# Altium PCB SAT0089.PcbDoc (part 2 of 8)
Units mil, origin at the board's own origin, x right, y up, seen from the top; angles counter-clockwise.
Board outline 4075 x 2715 mil, 6 copper layers (Top Layer, InternalPlane1, MidLayer1, Internal Plane 3, InternalPlane2, Bottom Layer), stack 67.4 mil thick; 538 components, 405 nets, 1716 pads, 1236 vias.
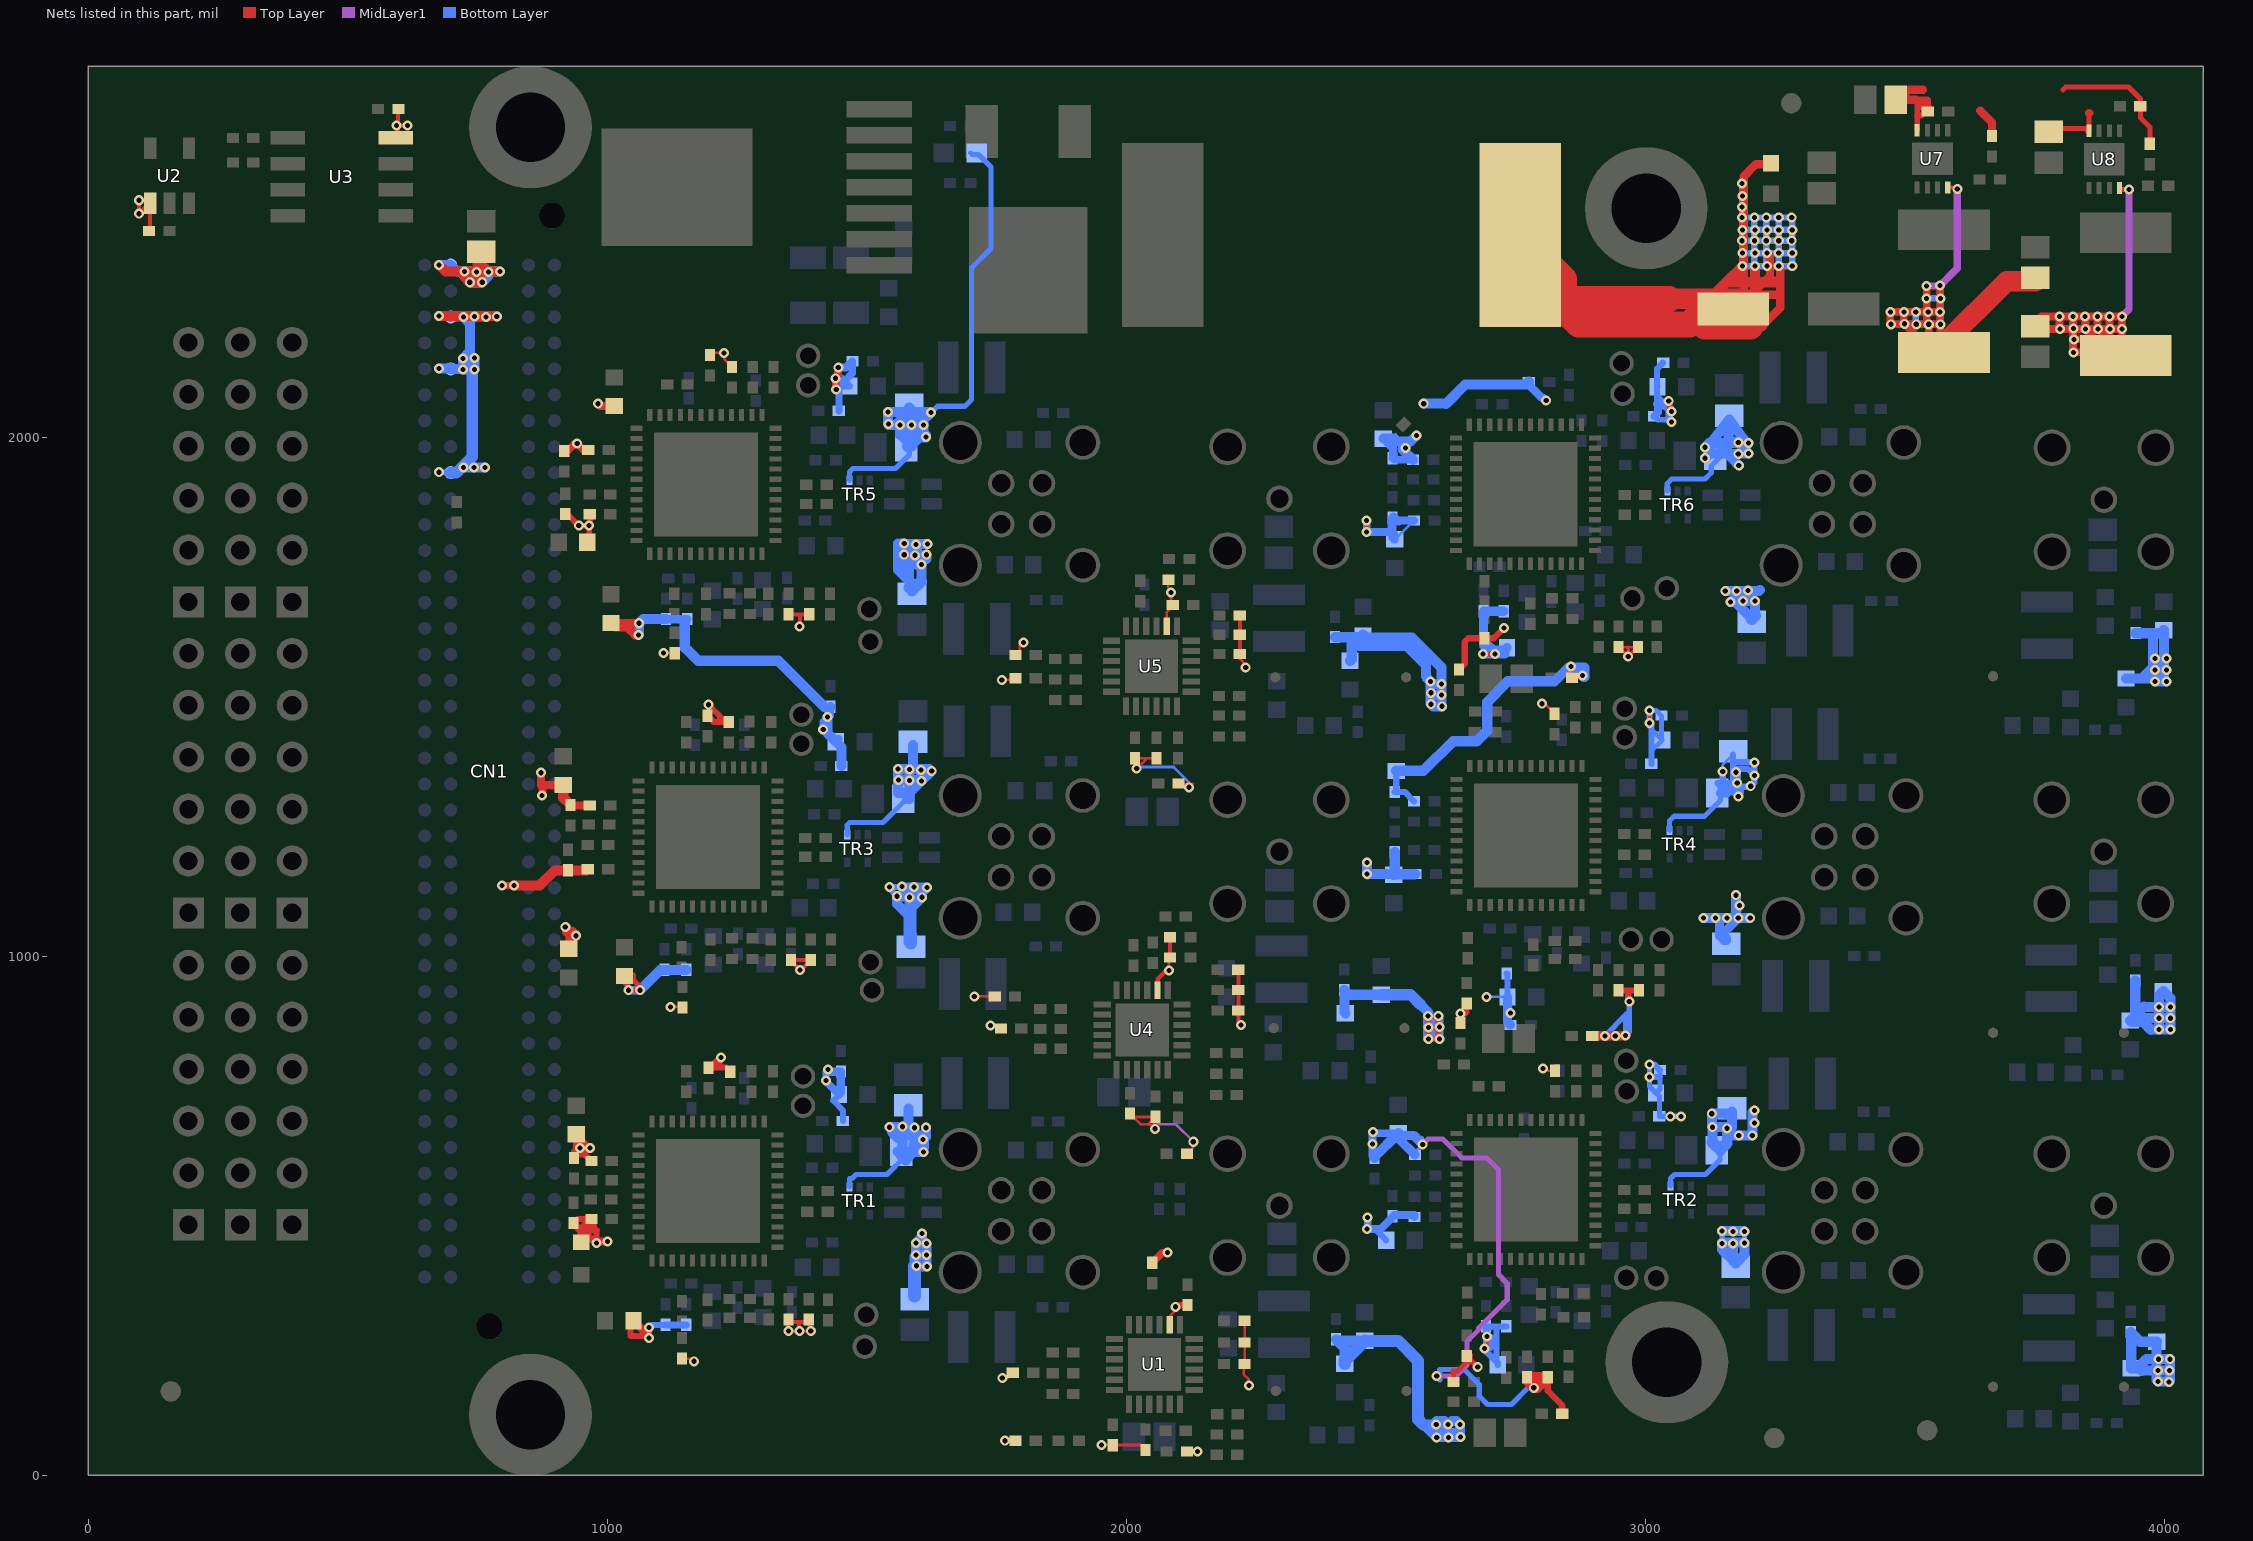
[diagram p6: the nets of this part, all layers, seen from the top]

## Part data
C1 C12 C13 C14 C15: "CAP, CERM, 10uF, 10V, +/-10%, X7R, 0805"
C2 C3 C4 C5 C6 C16 C18 C23 C24 C25 C27 C28 C30 C31 C32 C33 C35 C36 C37 C41 C44 C45 C48 C50 C55 C56 C57 C59 C60 C62 C63 C64 C65 C67 C68 C69 C73 C77 C79 C80 C82 C87 C88 C89 C91 C92 C94 C95 C96 C97 C99 C100 C101 C105 C109 C111 C112 C115 C119 C120 C121 C123 C126 C127 C129 C130 C131 C132 C133 C134 C136 C141 C142 C144 C146 C151 C152 C153 C155 C156 C158 C159 C160 C161 C163 C164 C165 C169 C173 C175 C176 C178 C183 C184 C185 C186 C187 C189 C190 C191 C192 C194 C195 C196 C200 C204 C206 C208 C209 C210 C211 C212 C213: "CAP, CERM, 0.1uF, 16V, +/-10%, X7R, 0402"
C7 C8: "CAP, CERM, 10uF, 25V, +/-10%, X7R, 1206"
C9: "CAP, CERM, 0.1uF, 50V, +/-10%, X7R, 0603"
C10: "CAP, CERM, 0.01uF, 50V, +/-10%, X7R, 0603"
C11: "CAP, AL, 82uF, 10V, +/-20%, 0.023 ohm, SMD"
C17 C19 C29 C34 C38 C39 C40 C42 C43 C46 C49 C51 C61 C66 C70 C71 C72 C74 C76 C78 C81 C83 C93 C98 C102 C103 C104 C106 C108 C110 C113 C114 C124 C125 C128 C135 C137 C138 C140 C143 C145 C147 C157 C162 C166 C167 C168 C170 C172 C174 C177 C179 C188 C193 C197 C198 C199 C201 C203 C205: "CAP CER 4.7UF 25V 10% X5R 0603"
C20 C21 C52 C53 C84 C85 C116 C117 C148 C149 C180 C181: "CAP CER 0.1UF 100V 10% X7R 0603"
C22 C54 C86 C118 C150 C182: "CAP, CERM, 10uF, 16V, +/-10%, X5R, 0805"
C26 C58 C90 C122 C154 C207: "CAP, CERM, 0.047uF, 16V, +/-10%, X7R, 0402"
C47 C75 C107 C139 C171 C202: "CAP, CERM, 22uF, 6.3V, +/-10%, X5R, 0805"
CN1: "Samtec 50 MIL Pitch Thermal Array Assembly"
CN2 CN3 CN4: library part "3X6 Header 100 MIL PITCH", "3X6 Header 100 MIL PITCH"
CN5 CN7 CN9 CN11 CN13 CN15: "Straight Plug PCB"
CN6 CN8 CN10 CN12 CN14 CN16: "Straight Plug"
D1: "Diode, Schottky, 40V, 7A, DPAK"
FID1 FID2 FID3 FID4 FID5 FID6: "Fiducial mark.  There is nothing to buy or mount."
L1: "Inductor, Drum Core, Ferrite, 4.7uH, 8.5A, 0.0088 ohm, SMD"
L2 L3: "INDUCTOR 2.2UH 1300MA 2220 10%"
L4 L5 L14 L15 L24 L25 L34 L35 L44 L45 L54 L55: "Fixed Inductors Power Inductor 10 uH 10 % 0.59 A"
L6 L16 L26 L36 L46 L56: "CHOKE COMMON MODE 67 OHM 0805"
L7 L17 L27 L37 L47 L57: "FERRITE CHIP 1000 OHM 400MA 0603"
L8 L18 L28 L39 L48 L58: "Fixed Inductors Power Inductor 4.7 uH 10 % 0.95 A"
L9 L19 L29 L38 L49 L59: "Fixed Inductors Power Inductor 100 uH 20 % 1.15 A"
L10 L11 L12 L13 L20 L21 L22 L23 L30 L31 L32 L33 L40 L41 L42 L43 L50 L51 L52 L53 L60 L61 L62 L63: "FERRITE CHIP 1000 OHM 0402"
LD1: "LED, Red, SMD"
Logo1: library part TI_Logo, "Texas Instrument Corporate Signature"
R1 R38 R39 R45 R63 R71 R87 R95 R111 R119 R136 R143 R167: "RES, 0 ohm, 5%, 0.063W, 0402"
R2 R13: "RES, 1.00k ohm, 1%, 0.063W, 0402"
R3: "RES, 15.0k ohm, 1%, 0.063W, 0402"
R4 R5 R6 R9 R12 R17 R18 R19 R20 R21 R22: "RES, 10.0k ohm, 1%, 0.063W, 0402"
R7: "RES, 13.0k ohm, 1%, 0.063W, 0402"
R8 R48 R64 R72 R96 R120 R135 R144 R159 R168: "RES, 3.01k ohm, 1%, 0.063W, 0402"
R10: "RES, 4.99k ohm, 1%, 0.063W, 0402"
R11 R49 R73 R88 R97 R121 R145 R160 R169: "RES, 11.0k ohm, 1%, 0.063W, 0402"
R14: "RES, 5.90k ohm, 1%, 0.1W, 0603"
R15: "RES, 61.9k ohm, 1%, 0.063W, 0402"
R16: "RES, 270 ohm, 5%, 0.125W, 0805"
R23 R24 R25 R50 R51 R52 R74 R75 R76 R98 R99 R101 R122 R123 R124 R146 R147 R148: "RES, 0 ohm, 5%, 0.125W, 0805"
R26 R27 R53 R54 R77 R78 R100 R102 R125 R126 R149 R150: "RES 1.0K OHM 1/10W 5% 0603 SMD"
R28 R29 R30 R55 R56 R57 R79 R80 R81 R103 R104 R105 R127 R128 R129 R151 R152 R153: "RES, 49.9 ohm, 1%, 0.063W, 0402"
R31 R34 R35 R44 R47 R59 R60 R68 R69 R83 R84 R92 R93 R107 R108 R116 R117 R131 R132 R140 R141 R155 R156 R164 R165 R172 R175 R178 R181 R184: "RES 10K OHM 1/16W .1% 0402 SMD"
R32 R36 R37 R58 R61 R62 R82 R85 R86 R106 R109 R110 R130 R133 R134 R154 R157 R158 R185 R186 R187 R188 R189 R190: "RES, 33 ohm, 5%, 0.063W, 0402"
R33 R40 R170 R171 R173 R174 R176 R177 R179 R180 R182 R183: "RES, 130 ohm, 5%, 0.063W, 0402"
R41 R42 R43 R46 R65 R66 R67 R70 R89 R90 R91 R94 R113 R114 R115 R118 R137 R138 R139 R142 R161 R162 R163 R166: "RES, 2.2k ohm, 5%, 0.063W, 0402"
R112: "RES, 100k ohm, 1%, 0.063W, 0402"
TP1 TP2 TP3 TP4 TP5 TP6 TP7 TP8 TP9 TP10 TP11 TP12 TP13 TP14 TP15 TP16 TP17 TP18 TP19 TP20 TP21 TP22 TP23 TP24: library part TP-032_RND, "Test Point, O.032 Hole"
TR1 TR2 TR3 TR4 TR5 TR6: "Low-Capacitance + / - 15 kV ESD-Protection Array for High-Speed Data Interfaces, 2 Channels, -40 to +85 degC, 5-pin SOT (DRL), Green (RoHS & no Sb/Br)"
U1 U4 U5: "IC I/O EXPANDER I2C 16B 24QFN"
U2: "IC ACCEL SMBUS DUAL TSOT23-5"
U3: "IC EEPROM 2KBIT 1MHZ 8SOIC"
U6: "5A SIMPLE SWITCHER®, Step-Down Voltage Regulator with Synchronization or Adjustable Switching Frequency, 7-pin TO-263 Thin, Pb-Free"
U7 U8: "2MHz, 600mA Step-Down DC-DC Converter with Mode Control, 8-pin LLP, Pb-Free"
U9 U10 U11 U12 U13 U14: "FPD-Link III Serializer and Deserializer, RHS0048A"
ZZ2 ZZ3 ZZ4: library part AssemblyNote

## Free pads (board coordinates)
  round 236.22 hole 133.86: 0(852.01,117.01) 0(852.01,2597.32) 0(3001.6,2441.8) 0(3041.61,218.43)
  round 39.37 smd paste-1000 mask-1000: 0(3248.31,72.01)

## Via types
v1: diameter 19.29, hole 9.84, Top Layer to Bottom Layer, tented both sides, 1155 vias
v2: diameter 19.68, hole 7.87, Top Layer to Bottom Layer, tented both sides, 80 vias
v3: diameter 22, hole 10, Top Layer to Bottom Layer, tented both sides, 1 vias

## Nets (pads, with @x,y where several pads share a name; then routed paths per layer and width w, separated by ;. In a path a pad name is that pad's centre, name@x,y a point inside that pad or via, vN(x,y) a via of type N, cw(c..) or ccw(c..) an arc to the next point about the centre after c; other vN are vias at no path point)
+1V8: C12.1 C28.1 C29.1 C60.1 C61.1 C92.1 C93.1 C132.1 C140.1 C156.1 C157.1 C187.1 C188.1 L2.2 L10.2 L20.2 L30.2 L40.2 L50.2 L60.2 R34.1 R35.1 R44.1 R59.1 R60.1 R68.1 R83.1 R84.1 R92.1 R107.1 R108.1 R116.1 R131.1 R132.1 R140.1 R155.1 R156.1 R164.1 U7.4 | length 5438.5
  Top Layer w5: v1@940,635 941,635 945,631 v1(947,631) ; R35.1@1349,300 1347,298 1347,280 v1(1349,278) v1(1370,278) v1(1392,278) 1391,279 1388,279 R34.1@1388,300 ; v1(1738,867) 1738,866 1753,866 R92.1@1758,861 ; v1(1760,1533) 1777,1533 1780,1536 R140.1@1786,1536 ; v1(1761,188) 1771,188 R44.1@1781,198 ; v1(2857,1559) 2857,1539 2860,1536 2874,1536 v1(2879,1541) ; R156.1@2948,1596 2949,1596 2967,1596 2985,1596 R155.1@2986,1596
  Top Layer w7: R156.1@2949,1596 v1(2967,1578) ; 2967,1596 v1(2967,1578) ; R155.1@2985,1596 v1(2967,1578)
  Top Layer w7.87: R35.1@1349,300 1353,296 1369,296 ; v1(1370,278) 1369,279 1369,296 ; R34.1@1388,300 1384,296 1369,296 ; R84.1@1354,991 v1(1371,974) 1373,974 1392,993 1354,993 R84.1@1354,991
  Top Layer w8: R132.1@1349,1659 1371,1659 ; v1(1370,1636) 1371,1637 1371,1659 ; R131.1@1389,1659 1371,1659 ; U7.4@3582.98,2481.43 3598.57,2481.43 v1(3601,2479)
  Top Layer w11.81: R108.1@2948.28,934.37 2967,934.37 ; v1(2969,913) 2967,915 2967,934.37 ; R107.1@2987.65,934.37 2967,934.37
  Top Layer w12: C28.1@936,612 C28.1@936,619 ; C29.1@940,648 940,635 940,624 936,624 C28.1@936,619 ; L10.2@969,606 956,619 C28.1@936,619 ; R59.1@2812,189 2812,163 2840,135 R68.1@2840,119
  Top Layer w15: v1(872,1354) 872,1330 875,1330 ; v1(874,1310) 875,1311 875,1330 ; C93.1@915,1330.5 875.5,1330.5 875,1330 ; C156.1@917,1974 923,1974 937,1988 v1(942,1988) 954,1976 L50.2@963,1976 ; C92.1@929,1292 930,1291 L30.2@966,1291 ; v1(982,2065) 986.5,2060.5 C157.1@1013,2060.5 ; v1(3542,2292) v1(3542,2268) v1@3542,2242 ; v1(3568,2293) v1@3568,2268 ; v1(3569,2218) v1@3568,2218 ; v1(3569,2268) v1@3568,2268 ; v1(3498,2242) 3498,2220 v1(3499,2219) ; v1(3498,2242) v1(3521,2242) v1@3542,2242 ; v1(3498,2242) v1(3472,2242) 3472,2219 v1(3473,2218) v1@3499,2218 ; v1@3499,2218 v1(3499,2219) ; v1@3499,2218 v1@3500,2218 ; v1(3499,2219) v1@3500,2218 ; v1@3500,2218 v1(3522,2218) v1(3546,2218) ; v1@3500,2218 3555.47,2162.53 3575.11,2162.53 L2.2@3568,2169.64 ; v1@3542,2242 v1(3545,2242) v1(3568,2242) ; v1@3542,2242 3542,2222 v1(3546,2218) ; v1(3546,2218) 3546,2191.64 L2.2@3568,2169.64 ; v1(3546,2218) v1@3568,2218 ; L2.2@3568,2169.64 v1@3568,2218 ; v1@3568,2218 v1(3568,2242) ; v1(3568,2242) v1@3568,2268
  Top Layer w18: R116.1@2898,847 v1(2922,847) v1(2942,847) 2961,847 v1(2962,848)
  Top Layer w19.29: C29.1@940,648 C29.1@940,652 ; C29.1@940,657.5 C29.1@940,657.44 C29.1@940,652 ; v1(947,631) v1@961,631 ; v1(967,631) v1@961,631 ; R60.1@2772,189 2772,182 v1(2785,169) ; C29.1@940,652 v1@961,631
  Top Layer w19.68: C93.1@915,1330.5 C93.1@915,1330.44 915,1306 C92.1@929,1292
  Top Layer w20: R60.1@2772,189 2812,189 2792,169 v1(2785,169)
  Top Layer w39: L2.2@3575.11,2162.53 3575.11,2180.11 3696,2301 C12.1@3751,2301
  MidLayer1 w9.84: v1(2571,638) 2581,648 2610,648 2646,612 2694,612 2717,589 2717,387 2734,370 2734,339 2679,284 2679,281 2656,258 2656,212 2636,192 v1(2598,192)
  MidLayer1 w13.78: v1(3499,2219) v1@3499,2218 ; v1(3569,2268) v1@3568,2268 ; v1(3601,2479) 3601,2326 v1(3568,2293) ; v1@3499,2218 v1(3473,2218) 3472,2219 v1(3472,2242) v1(3498,2242) v1(3521,2242) v1@3542,2242 ; v1@3499,2218 v1(3522,2218) v1(3546,2218) ; v1@3542,2242 v1(3545,2242) v1(3568,2242) ; v1@3542,2242 3542,2222 v1(3546,2218) ; v1@3542,2242 v1(3542,2268) v1(3542,2292) 3567,2292 v1(3568,2293) ; v1(3546,2218) v1(3569,2218) 3568,2219 v1(3568,2242) ; v1(3568,2242) v1@3568,2268 ; v1@3568,2268 v1(3568,2293)
  Bottom Layer w5: C188.1@2495,1997.5 2498.5,2001 2514,2001 2519,2006 ; L20.2@2556,618 2556,623 v1(2571,638)
  Bottom Layer w10: v1(2598,192) v1@2604,186 ; 2604,184 v1@2604,186 ; v1(2785,169) 2774,169 2742,137 2696,137 2680,153 2680,175 2651,204 2604,204 v1@2604,186 ; v1(2922,847) v1@2923,848 ; v1(2942,847) v1@2942,848 ; v1(2969,913) 2969,894 ; v1@2923,848 v1@2942,848 ; v1@2923,848 2962,887 ; v1@2942,848 v1(2962,848) ; v1(2962,848) 2969,855 2969,894 ; v1(2962,848) 2962,887 ; 2962,887 2969,894
  Bottom Layer w12: C140.1@2520,1357.5 C140.1@2520,1357.44 2520,1320 2517,1317 2536,1317 L40.2@2554,1299 ; v1(3569,2268) v1@3568,2268 ; v1(3498,2242) 3498,2220 v1(3499,2219) v1@3499,2218 ; v1(3498,2242) v1(3521,2242) ; v1(3498,2242) v1(3472,2242) 3472,2219 v1(3473,2218) v1@3499,2218 ; v1@3499,2218 v1(3522,2218) ; v1(3521,2242) 3521,2219 v1(3522,2218) ; v1(3521,2242) v1@3542,2242 ; v1(3522,2218) v1(3546,2218) ; v1@3542,2242 v1(3545,2242) v1(3568,2242) ; v1@3542,2242 3542,2222 v1(3546,2218) ; v1@3542,2242 v1(3542,2268) ; v1(3542,2268) v1(3542,2292) 3567,2292 v1(3568,2293) v1@3568,2268 ; v1(3542,2268) v1@3568,2268 ; v1(3546,2218) v1(3569,2218) 3568,2219 v1(3568,2242) ; v1(3568,2242) v1@3568,2268
  Bottom Layer w15: C60.1@2478,612 2474,616 v1(2474,639) 2474,661 v1(2475,662) 2477.5,659.5 C61.1@2524,659.5 ; C188.1@2495,1997.5 2510,1982.5 2514,1982.5 2514,1961 2513,1960 2516,1957 2532,1957 ; 2533,1957 L60.2@2552,1957
  Bottom Layer w18: L20.2@2556,618 2525,649 2524,649 C61.1@2524,659.44 2524,659.5 2528.5,655 2554,655 2564,645 2565,645 v1@2566,646
  Bottom Layer w19.29: C60.1@2478,612 2478,613.5 C61.1@2524,659.5 ; C188.1@2495,1997.5 2516.5,1997.5 2522,1992 2547,1992 v1(2559,2004) ; v1@2532,1985 2533,1985 v1(2538,1980) 2535,1977 2532,1977 L60.2@2552,1957 ; 2825,1530 2852,1557 2858,1557 v1@2858,1558 ; v1(2857,1559) v1@2858,1558 ; v1(2879,1541) 2882,1538 2883,1538 2883,1557 2859,1557 v1@2858,1558
  Bottom Layer w20: C140.1@2520,1357.5 2572.5,1357.5 2630,1415 2675,1415 2695,1435 2695,1490 2735,1530 2825,1530
+1V8_A: C13.1 C41.1 C42.1 C45.1 C46.1 C73.1 C74.1 C77.1 C78.1 C105.1 C106.1 C109.1 C110.1 C124.1 C134.1 C136.1 C137.1 C169.1 C170.1 C173.1 C174.1 C200.1 C201.1 C204.1 C205.1 L3.2 L12.2 L13.2 L22.2 L23.2 L32.2 L33.2 L41.2 L43.2 L52.2 L53.2 L62.2 L63.2 U8.4 | length 5422.5
  Top Layer w5: C106.1@1033,962.5 1031,964.5 1031,966.5 1051,966.5 1053,964.5 1053,952 ; v1(1041,935) v1@1037,935 ; v1(2690,245) 2695,250 v1(2695,268) ; v1(3008,1450) v1(3008,1474) ; v1@1037,935 1035,935 1036,936 v1@1037,935
  Top Layer w8: v1(1041,935) v1(1063,935)
  Top Layer w9.84: U8.4@3913.69,2477.49 3931.49,2477.49 v1(3932,2478)
  Top Layer w10: v1(1041,935) 1041,942 1030,953 1033,956 C106.1@1033,962.44 1033,962.5 1041.5,954 1051,954 1053,952 1063,942 v1(1063,935) ; v1(2687,1583) v1(2710,1583)
  Top Layer w11.81: C42.1@1050.5,298 1045,298 1045,269 v1@1076,269 ; v1@1079,284 1077,282 1077,271.5 1077,269 v1@1076,269 ; v1(1080,265) v1@1076,269
  Top Layer w15: C42.1@1050.5,298 1077,271.5 1079,269.5 1079,284 v1(1080,285) ; v1(1441,2092) 1440,2093 v1(1440,2114) 1445,2119 v1(1445,2135) ; v1@3048,2057 v1@3048,2054 ; v1(3050,2050) v1@3049,2051 ; v1@3048,2054 3048,2052 v1@3049,2051 ; v1@3048,2054 3049,2054 v1@3049,2051 ; v1(3798,2233) 3798,2210 v1(3799,2209) ; v1(3798,2233) v1(3824,2233) ; v1(3798,2233) 3763,2233 3751,2221 3763,2209 v1(3799,2209) ; v1(3799,2209) v1@3824,2209 ; v1@3824,2189 v1(3826,2189) L3.2@3868,2189 ; v1@3824,2189 v1@3824,2209 ; v1@3824,2189 3824,2165 v1(3825,2164) L3.2@3893,2164 ; v1@3824,2209 v1@3824,2210 ; v1@3824,2209 v1@3825,2209 ; v1@3824,2210 v1(3825,2210) v1@3825,2209 ; v1@3824,2210 v1(3824,2233) ; v1(3824,2233) v1(3847,2233) ; v1@3825,2209 v1(3848,2209) ; v1(3847,2233) 3848,2232 v1(3848,2209) ; v1(3847,2233) v1(3871,2233) ; v1(3848,2209) v1(3872,2209) v1@3873.13,2209 ; v1(3848,2209) L3.2@3868,2189 ; L3.2@3868,2189 L3.2@3893.13,2189 ; L3.2@3868,2189 L3.2@3893,2164 ; v1(3871,2233) 3871,2211.13 v1@3873.13,2209 ; v1(3871,2233) v1(3894,2233) ; v1@3873.13,2209 v1@3894,2209 ; v1@3873.13,2209 L3.2@3893.13,2189 ; L3.2@3893,2164 L3.2@3918.13,2164 ; L3.2@3893,2164 3900.38,2156.62 3925.5,2156.62 L3.2@3924.78,2157.34 ; L3.2@3893.13,2189 L3.2@3894,2188.13 ; L3.2@3894,2188.13 L3.2@3918.13,2164 ; L3.2@3894,2188.13 v1@3894,2209 ; v1@3894,2209 v1(3895,2209) v1(3918,2209) ; v1@3894,2209 v1(3894,2233) ; v1(3894,2233) v1(3918,2233) v1(3918,2209) ; v1(3918,2209) 3918,2164.13 L3.2@3918.13,2164 ; L3.2@3918.13,2164 L3.2@3924.78,2157.34 ; L3.2@3918.13,2164 L3.2@3924.78,2157.34
  Top Layer w16: C170.1@1007,1642.5 C170.1@1007.5,1642 ; v1(1060,1619) 1053,1619 1038,1634 ; v1(1061,1642) 1046,1642 ; C170.1@1007.5,1642 1015.5,1634 1038,1634 ; C170.1@1007.5,1642 1046,1642 ; 1038,1634 1046,1642
  Top Layer w19.29: L3.2@3913.88,2145 L3.2@3925.5,2156.62
  MidLayer1 w13.78: v1(3825,2164) v1@3825,2189 ; v1(3826,2189) v1@3825,2189 ; v1(3932,2478) 3932,2247 v1(3918,2233) ; v1(3824,2233) 3825,2232 v1(3825,2210) v1@3825,2209 ; v1(3824,2233) v1(3847,2233) ; v1(3824,2233) v1(3798,2233) 3798,2210 v1(3799,2209) v1@3825,2209 ; v1@3825,2189 v1@3825,2209 ; v1@3825,2209 v1(3848,2209) ; v1(3847,2233) 3847,2210 v1(3848,2209) ; v1(3847,2233) v1(3871,2233) v1(3894,2233) ; v1(3848,2209) v1(3872,2209) v1(3895,2209) ; v1(3894,2233) 3894,2210 v1(3895,2209) ; v1(3894,2233) v1(3918,2233) ; v1(3895,2209) v1(3918,2209) v1(3918,2233)
  Bottom Layer w5: v1(2694,922) C137.1@2734.44,922 C137.1@2734.5,922
  Bottom Layer w9: v1(3008,1450) 3008,1441.5 3011.81,1437.69 C124.1@3031,1418.5 ; v1(3008,1474) 3021,1474 3031,1464 C124.1@3031,1418.5 ; 3011.81,1396.31 3032.5,1417 C124.1@3031,1418.5
  Bottom Layer w10: v1(2690,245) 2693,245 2702,245 v1@2702,267 ; C73.1@2693,287 2690,284 2693,284 C73.1@2695,284 ; v1(2695,268) C73.1@2695,284 ; C73.1@2699,287 2702,284 C73.1@2695,284 ; v1(3008,792) v1(3008,768) 3008,749.5 C78.1@3020.5,737 ; L63.2@3017,2041 3024,2034 3048,2034 3049,2034 v1@3049,2031 ; C77.1@3028,781 3028,768 3028,744.5 C78.1@3020.5,737 ; v1(3069,692) v1(3048,692) 3027,692 3027,730.5 C78.1@3020.5,737
  Bottom Layer w11.81: v1(1080,265) 1079,266 v1@1079,282 ; v1(1080,285) 1079,284 v1@1079,282 ; C41.1@1112,290 1087,290 v1@1079,282 ; C46.1@1445,735.5 1447,735.5 1446.5,735 1446.5,734 1435,722.5 1454,703.5 L13.2@1454,683 ; v1(3008,768) 3028,768 ; v1(3008,792) 3017,792 C77.1@3028,781 ; v1(3008,1474) v1(3008,1450) 3011.81,1446.19 3011.81,1437.69 3011.81,1396.31 L43.2@3011.81,1371.19
  Bottom Layer w12: v1(2695,268) v1@2695,267 ; v1@2702,267 v1@2695,267 ; C74.1@2715.5,213 2715.5,217 C74.1@2713,219.5 ; L22.2@2732,287 2713,287 ; L41.2@2733,967 2734.5,965.5 C137.1@2734.5,922 ; L63.2@3022.5,2046.5 3022.5,2064.5 3022.5,2079.5 ; C204.1@3034,2144 3022.5,2132.5 3022.5,2099 3023.5,2098 3022.5,2097 3022.5,2079.5 ; v1@3039,2063 3037.5,2064.5 3022.5,2079.5 ; v1@3048,2052 3048,2053 3047,2053 3045,2053 3045,2037 3048,2037 3048,2034 3048,2032 3049,2031 v1(3050,2030) ; v1(3825,2164) 3824,2165 v1@3824,2189 ; v1(3826,2189) v1@3824,2189 ; v1@2693,267 2693,245 2693,239.5 C74.1@2713,219.5 ; v1@2693,267 2693,284 2693,287 2699,287 2713,287 ; v1@2693,267 v1@2695,267 ; C74.1@2713,219.5 2713,287 ; v1@3824,2189 v1@3824,2209 ; v1@3824,2209 v1(3799,2209) 3798,2210 v1(3798,2233) v1(3824,2233) ; v1@3824,2209 v1@3825,2209 ; v1@3824,2209 v1@3824,2210 ; v1@3824,2210 v1(3825,2210) v1@3825,2209 ; v1@3824,2210 v1(3824,2233) ; v1(3824,2233) v1(3847,2233) ; v1@3825,2209 v1(3848,2209) ; v1(3847,2233) 3847,2210 v1(3848,2209) ; v1(3847,2233) v1(3871,2233) ; v1(3848,2209) v1(3872,2209) ; v1(3871,2233) 3871,2210 v1(3872,2209) ; v1(3871,2233) v1(3894,2233) ; v1(3872,2209) v1(3895,2209) ; v1(3894,2233) 3894,2210 v1(3895,2209) ; v1(3894,2233) v1(3918,2233) v1(3918,2209) v1(3895,2209)
  Bottom Layer w13.78: C41.1@1112,290 L12.2@1152,290 ; v1(1416,1437) v1@1416,1438.5 ; 1416,1453 v1@1416,1438.5 ; 1424,1430.5 1417.5,1437 v1@1416,1438.5 ; v1(1425,782) 1421,778 v1(1421,761) 1421,759.5 1445,735.5 C46.1@1446.5,734 ; v1(1441,2092) 1440,2093 v1(1440,2114) 1451.5,2114 C174.1@1457,2108.5 ; L53.2@1446.22,2051.26 1446.22,2096.72 1448.5,2099 ; C173.1@1472,2147 1472,2123.5 C174.1@1457,2108.5 ; v1@2692.5,1583 v1@2694.5,1581 ; C201.1@2730.5,1592 2717.5,1592 ; 1448.5,2099 C174.1@1466.44,2099 1466.5,2099 C174.1@1457,2108.5 ; 1448.5,2099 1448,2099.5 C174.1@1457,2108.5 ; v1@2694.5,1581 2697,1581 2699,1583 v1@2707.75,1591.75 ; v1@2694.5,1581 2695.75,1582.25 2695.75,1583 2695.75,1592 2695.75,1603.75 v1@2707.75,1591.75 ; v1@2707.75,1591.75 2708,1592 2717.5,1592 ; v1@2707.75,1591.75 2712.5,1587 2717.5,1592
  Bottom Layer w15: L52.2@1149,1645 L52.2@1154,1650 ; 1418,1481 C109.1@1430,1481 ; v1(1440,2114) 1445,2119 v1(1445,2135) 1460,2135 C173.1@1472,2147 ; C110.1@1440.5,1414 C110.1@1446,1419.5 ; L63.2@3017,2041 3022.5,2046.5 3025,2049 3025,2062 3024,2063 ; v1(3045,2070) 3039.5,2064.5 3037.5,2064.5 3022.5,2064.5 3024,2063 ; v1(3050,2050) 3048,2052 3047,2053 3046,2054 3046,2059 3039,2059 3039,2063 3024,2063
  Bottom Layer w16: C169.1@1113,1650 L52.2@1154,1650
  Bottom Layer w16.14: v1(1425,782) 1429,778 1450,778 1450,737.5 C46.1@1446.5,734
  Bottom Layer w17: v1(1041,935) v1(1063,935)
  Bottom Layer w17.72: v1(2687,1583) 2692.5,1583 2695.75,1583 2699,1583 v1(2710,1583) 2729.5,1583 2729.5,1591 2730.5,1592 C201.1@2733.5,1595 ; 2695.75,1592 2688,1599.75 2688,1665 L62.2@2727,1665
  Bottom Layer w18: C137.1@2734.5,922 v1@2734.5,891 ; C136.1@2740,868 2734.5,873.5 v1@2734.5,891 ; v1(2740,891) v1@2734.5,891
  Bottom Layer w19.29: v1(1060,1619) 1061,1620 v1(1061,1642) 1069,1650 C169.1@1113,1650 ; v1(1063,935) C105.1@1102,974 ; v1(1416,1437) 1417.5,1437 v1@1424,1437 ; 1424,1430.5 v1@1424,1437 ; C109.1@1430,1481 1427,1478 1427,1464 v1(1424,1461) v1@1424,1437 ; C110.1@1440.5,1414 1451,1403.5 L33.2@1451,1367
  Bottom Layer w19.68: C105.1@1102,974 L32.2@1152,974 ; 1424,1430.5 C110.1@1440.5,1414
  Bottom Layer w20: L52.2@1149,1645 1149,1595 1150,1595 1175,1570 1329,1570 1418,1481
+3V3: C1.1 C2.2 C3.1 C4.1 C5.2 C6.2 C33.1 C34.1 C65.1 C66.1 C97.1 C98.1 C127.1 C143.1 C161.1 C162.1 C192.1 C193.1 CN1.72 CN1.76 CN1.78 CN1.80 L11.2 L21.2 L31.2 L42.2 L51.2 L61.2 R2.2 R4.2 R7.2 R9.2 R10.2 R12.2 R31.1 R41.2 R42.2 R43.2 R46.1 R47.1 R65.2 R66.2 R67.2 R69.1 R70.1 R89.2 R90.2 R91.2 R93.1 R94.1 R113.2 R114.2 R115.2 R117.1 R118.1 R137.2 R138.2 R139.2 R141.1 R142.1 R161.2 R162.2 R163.2 R165.1 R166.1 R172.1 R175.1 R178.1 R181.1 R184.1 U1.8 U2.1 U3.8 U4.8 U5.8 | length 5444.4
  Top Layer w5: C98.1@936,1027.5 v1@941,1032.5 ; C34.1@950,445.5 955.5,451 v1@975,451 ; v1(1108,1585) 1129,1585 R181.1@1130,1584 ; v1(1122,903) 1143.06,903 R175.1@1144.72,901.34 ; R31.1@1144,225 1162,225 v1(1167,220) ; R89.2@1193,1464 1193,1483 v1(1195,1485) ; R137.2@1198,2159 1202,2163 v1(1225,2163) 1225,2151 R138.2@1240,2136 ; 1218,786 1219,787 v1@1219,804 ; v1(1707,923) R9.2@1746,923 ; v1(1766,67) R2.2@1786,67 ; R12.2@1779,1581 R12.2@1786.31,1581 1795,1581 1795,1602 1797,1602 1800,1605 v1(1802,1605) ; v1(1952,59) R43.2@1974,59 ; R91.2@2007,697 R91.2@2013.29,690.71 ; R139.2@2016.77,1381.65 R139.2@2021.35,1381.65 ; v1(2020,1362) v1@2021.35,1363.35 ; R46.1@2037,49 R46.1@2028,58 ; R142.1@2058.11,1381.65 2039.65,1381.65 ; U5.8@2077.8,1635.91 2077.8,1662.8 2089,1674 2089,1680 2086,1683 v1(2086,1701) 2081,1706 R10.2@2081,1726 ; v1(2082,973) 2082,991 2078.5,994.5 C5.2@2082,998 ; U1.8@2083.53,290.77 2085,292.24 2085,308 2096,319 2095,319 v1(2095,325) ; R141.1@2101,1333 2128,1333 v1(2121,1326) ; R47.1@2117,46 v1(2137,46) ; R93.1@2117,620 2128,631 2128,644 v1(2129,643) ; R118.1@2212,978.39 R118.1@2215.91,974.49 ; R161.2@2219,1583 2219,1573 2231,1561 2230,1560 v1(2230,1557) ; R70.1@2228,298 R65.2@2228,215 ; R65.2@2234,215 R65.2@2228,215 ; R69.1@2630,185 R69.1@2638,185 ; R165.1@2641,1553 R165.1@2642,1553 ; R172.1@2656,230 R172.1@2656,230.32 2656,233 2665,233 2665,221 2667,219 ; R184.1@2687,1613 2684,1616 2687,1616 R184.1@2690,1613 ; v1(2801,1487) 2806,1487 R114.2@2825,1468 ; v1(2803,784) 2802,785 v1@2802,790 ; R66.2@2826,780 2812,780 v1@2802,790 ; R43.2@1974,59 R43.2@1974,58.31 1974,58 R46.1@2028,58 ; R43.2@1974,59 2027,59 R46.1@2028,58 ; R91.2@2013.29,690.71 2027,677 2041,677 2042.43,675.57 ; R91.2@2013.29,690.71 R94.1@2056.14,690.71 ; v1@2021.35,1363.35 R139.2@2021.35,1381.65 ; v1@2021.35,1363.35 2039.65,1381.65 ; R139.2@2021.35,1381.65 2039.65,1381.65 ; 2042.43,675.57 2047.43,675.57 v1(2055,668) 2056.14,669.14 R94.1@2056.14,690.71 ; 2042.43,675.57 2042.43,677 R94.1@2056.14,690.71 ; R65.2@2228,215 2226,213 2226,195 2236,185 v1(2236,173) 2236,171 v1@2235,171 ; v1@2235,171 2235,169 2237,169 v1@2235,171 ; v1@2802,790 2802,791 2801,791 v1@2802,790
  Top Layer w8: v1(98,2457) v1(98,2431) U2.1@119.13,2452.13 ; C3.1@116.85,2397.72 119.13,2400 U2.1@119.13,2452.13 ; U2.1@119.13,2452.83 U2.1@119.13,2452.13 ; U3.8@593.21,2577.05 597,2580.83 v1@597,2601 ; v1(594,2601) v1@597,2601 ; C4.1@598,2633 597,2632 v1@597,2601 ; v1(615,2601) v1@597,2601 ; U4.8@2060.08,935.12 2060.58,935.62 2060.58,956.5 2076.58,972.5 2076.58,974.08 2078.5,976 2081.5,973 v1(2082,973) ; C5.2@2079,995.08 C5.2@2081.92,998 ; C5.2@2084,998 2082,998 C5.2@2081.92,998 ; R7.2@2084,1037 2084,1002.5 2079.5,998 C5.2@2081.92,998 ; R118.1@2215.91,974.49 2215.91,873.09 v1(2221,868) ; R161.2@2219,1583 R166.1@2219,1657 ; v1(2463,1818) v1(2463,1840) ; R117.1@2644,872 2643,873 2643,878 2656,891 ; v1(2644,890) 2646,892 2656,892 ; R178.1@2656,909 2656,892 ; 2656,891 2656,892 ; 2656,891 2657,892 2656,892
  Top Layer w10: R69.1@2630,180 2630,185 2630,201 2638,201 2656,219 2667,219 v1(2677,209)
  Top Layer w11: C161.1@919,1852 923,1852 v1(945,1830) v1(965,1830) ; C162.1@966.5,1798 965,1799.5 v1(965,1830) ; L51.2@967,1852 967,1832 v1(965,1830)
  Top Layer w11.02: v1(1195,1485) 1217,1463 1217,1458 1219,1458 1213,1452 ; R41.2@1201,786 1218,786 1229,786 R42.2@1237,778
  Top Layer w11.8: R165.1@2641,1553 2652,1564 2652,1606 2659,1613 2687,1613 2690,1613 2708,1613 v1(2728,1633)
  Top Layer w11.81: C98.1@928,1016.5 936,1016.5 C98.1@936,1027.5 ; C98.1@930,1018.5 C98.1@930,1019.5
  Top Layer w12: C33.1@935,486 943,494 969,494 969,481 974,481 974,472 ; v1(979,448) v1@979,451 ; 980,472 979,472 ; v1@982,451 v1@979,451 ; R89.2@1193,1464 1205,1452 1213,1452 R90.2@1234,1452 ; v1(2095,325) 2098,328 C2.2@2118,328 ; 974,472 956,472 954,472 956,470 975,451 v1@979,451 ; 974,472 979,472 ; v1@979,451 979,472
  Top Layer w13.78: v1(797,1137) v1(820,1137) ; R4.2@2050,410 2069,429 2078,429 v1(2079,430)
  Top Layer w15: C33.1@935,486 950,471 C34.1@950,449 C34.1@950,445.5 ; 956,470 956,472 956,481 L11.2@969,494 ; v1(979,448) 982,451 v1(1000,451)
  Top Layer w16: R41.2@1195,786 1201,786 1219,804 v1(1219,805)
  Top Layer w19.29: v1(676,2234) v1@723,2234 ; v1(676,2332) 688,2320 v1(725,2320) ; v1(723,2232) v1@723,2234 ; v1(744,2233) v1@744,2234 ; v1@750,2319 v1(748,2319) v1@748,2320 ; C1.1@757,2351 757,2333 v1@770,2320 ; v1(759,2299) 750,2299 v1(735,2299) 725,2309 v1(725,2320) ; v1(766,2232) v1@766,2234 ; v1(787,2233) 786,2234 v1@766,2234 ; v1(793,2320) v1@771,2320 ; v1(820,1137) 870,1137 899,1166 960,1166 L31.2@962,1168 ; v1(919,1057) 922,1054 922,1047 933,1047 v1(940,1040) 938,1038 929,1038 929,1019.5 930,1018.5 928,1016.5 C98.1@926,1014.5 ; v1@723,2234 v1@744,2234 ; v1(725,2320) v1@748,2320 ; v1@744,2234 v1@766,2234 ; v1@748,2320 750,2320 v1@770,2320 ; v1@770,2320 v1(771,2319) v1@771,2320 ; v1@770,2320 v1@771,2320
  Top Layer w20: v1@750,2299 750,2319 750,2320 750,2344 C1.1@757,2351
  MidLayer1 w5: v1(723,2232) v1@744,2232 ; v1(744,2233) v1@744,2232 ; v1(787,2233) 786,2232 v1(766,2232) v1@744,2232 ; v1(2055,668) 2053,670 2053,677 2095,677 v1(2129,643)
  Bottom Layer w5: v1(2020,1362) 2023,1365 2091,1365 2121,1335 v1(2121,1326) ; C66.1@2500.5,453 C66.1@2500.5,453.5 ; C193.1@2517,1803.5 2517.5,1803.5 L61.2@2554,1840
  Bottom Layer w10: v1(676,1933) 697.43,1933 CN1.72@698.27,1932.17 ; v1(797,1137) v1(820,1137)
  Bottom Layer w12: v1(2464,475) 2464,474 2479.5,474 C66.1@2500.5,453
  Bottom Layer w15: v1(2463,1840) v1(2463,1818) 2508,1818 C193.1@2512,1814 ; v1(2464,475) v1@2465,475 ; v1(2465,497) v1@2465,475 ; L61.2@2554,1840 2527,1840 2525,1838 2515,1848 C192.1@2513,1846 ; L21.2@2555,498 2555,502 2516,502 2513,499 2513,498 2490,475 v1@2465,475 ; C193.1@2512,1810.5 C193.1@2513,1811.5 ; C193.1@2512,1810.5 C193.1@2513,1809.5 ; C193.1@2512,1810.5 C193.1@2512,1814 ; C193.1@2512,1814 C193.1@2513,1814 ; C193.1@2512,1814 2512,1820.5 2511,1821.5 2511,1844 C192.1@2513,1846 ; C193.1@2513,1809.5 C193.1@2513,1811.5 ; C193.1@2513,1809.5 2517,1805.5 C193.1@2517,1803.56 2517,1803.5 2516,1803.5 2513,1806.5 C193.1@2513,1809.5 ; C193.1@2513,1811.5 C193.1@2513,1814 ; C193.1@2513,1811.5 2515.5,1814 C193.1@2513,1814 ; C193.1@2513,1814 C192.1@2513,1845.32 C192.1@2513,1846
  Bottom Layer w15.75: R162.2@2775,2107 2776,2106 2776,2101 2801,2076 2804,2076 v1(2809,2071)
  Bottom Layer w19.29: v1(676,2133) CN1.76@697.43,2133 ; v1(676,2234) v1@723,2234 ; v1(676,2332) CN1.80@698.1,2332 ; CN1.78@698.27,2232.17 699.1,2233 v1@723,2233 ; CN1.80@698.27,2332.17 710.43,2320 v1(725,2320) ; CN1.76@703,2132 721,2132 v1(722,2131) ; v1@719,1942 v1(723,1942) ; v1@721,1944 v1(723,1942) ; v1(764,1942) v1(743,1942) v1(723,1942) ; v1(787,2233) 786,2234 v1@766,2234 ; v1(793,2320) v1@771,2320 ; v1(2464,1181) v1(2464,1159) 2465,1158 2466,1159 2516.5,1159 2557,1159 2555.5,1157.5 C143.1@2515,1157.5 ; v1(2573,2065) 2616,2065 ; v1(722,2131) 740,2131 v1(744,2131) v1(744,2153) 727,2153 v1@723,2153 ; v1(722,2131) v1(722,2152) v1@723,2153 ; v1@723,2153 735,2165 735,2220 v1(723,2232) v1@723,2233 ; v1@723,2233 v1@723,2234 ; v1@723,2233 v1(744,2233) ; v1@723,2234 v1@744,2234 ; v1(725,2320) 725,2309 v1(735,2299) v1(759,2299) ; v1(725,2320) v1@748,2320 ; v1(744,2233) 765,2233 v1(766,2232) v1@766,2234 ; v1(744,2233) v1@744,2234 ; v1@744,2234 v1@766,2234 ; v1@748,2320 v1(748,2319) 748,2310 v1(759,2299) ; v1@748,2320 v1@771,2320 ; v1(759,2299) 771,2311 v1(771,2319) v1@771,2320
  Bottom Layer w20: CN1.76@697.43,2133 CN1.76@698.27,2132.17 702.83,2132.17 CN1.76@703,2132 ; CN1.80@698.1,2332 CN1.80@698.27,2332.17 ; C143.1@2515,1157.5 2516.5,1159 2517,1159.5 C127.1@2517,1201 ; 2616,2065 2653,2102 2770,2102 R162.2@2775,2107
  Bottom Layer w22.05: CN1.72@698.27,1932.17 709.17,1932.17 719,1942 721,1944 740,1963 740,2131 740,2140 v1@727,2153
+5V: C11.1 C14.1 C15.1 C18.1 C19.1 C22.1 C50.1 C51.1 C54.1 C82.1 C83.1 C86.1 C113.1 C115.1 C118.1 C146.1 C147.1 C150.1 C178.1 C179.1 C182.1 L1.2 L7.2 L17.2 L27.2 L37.2 L47.2 L57.2 LD1.1 R14.2 R17.2 R18.2 R20.2 R22.2 R23.2 R24.2 R50.2 R51.2 R74.2 R75.2 R98.2 R99.2 R122.2 R123.2 R146.2 R147.2 TR1.1 TR2.1 TR3.1 TR4.1 TR5.1 TR6.1 U7.8 U8.8 | length 13754.7
  Top Layer w9.84: U7.8@3523.93,2591.66 3523.93,2620 3523.93,2645.07 ; C15.1@3777,2595 3847.36,2595 3854.64,2587.72 3854.64,2624.64 ; 3805,2670 3810,2675 3931,2675 3954,2652 3954,2616 3972,2598 R22.2@3972,2566 ; v1@2581,863 v1(2581,885) v1(2601,885) v1@2601,864 ; v1@2581,863 2581,842 v1(2582,841) v1(2603,841) 2601,843 v1@2601,863 ; v1@2581,863 v1(2582,863) v1@2601,863 ; v1@2601,863 v1@2601,864 ; v1@2601,863 2602,863 v1(2603,864) v1@2601,864
  Top Layer w11.81: C14.1@3489.06,2650.72 C14.1@3492,2647.78 ; 3518.28,2650.72 3523.93,2645.07 ; 3521.28,2650.72 3543.3,2650.72 3544,2650.02 R17.2@3544,2632 ; 3523.93,2620 3532,2620 3542,2630 R17.2@3544,2632 ; R17.2@3544,2632 3544,2628 3547.24,2631.24 3547.24,2635.24 R17.2@3544,2632
  Top Layer w16: v1(3186,2379) v1@3189.28,2379 ; v1(3186,2424) v1@3189.28,2424 ; v1(3186,2444) v1@3189.28,2444 ; v1(3186,2489) v1@3189.28,2489 ; v1(3187,2330) v1@3189.28,2330 ; v1(3187,2355) v1@3189.28,2355 ; v1(3187,2400) v1@3189.28,2400 ; v1(3187,2465) v1@3189.28,2465 ; C11.1@3191.54,2267 3189.28,2269.26 3189.28,2299 v1@3189.28,2330 ; C11.1@3193.54,2265 C11.1@3203.28,2274.73 ; 3203,2214 3224,2214 3225,2215 3260,2250 3260,2270 ; v1@3240,2350 3240,2311.46 3227.54,2299 3211,2282.46 C11.1@3203.28,2274.73 ; LD1.1@3240,2533.47 3233,2526.47 3213.47,2526.47 3189.28,2502.28 v1@3189.28,2489 ; v1@3260,2330 3260,2270 ; 3535,2670 3508.35,2670 3489.06,2650.72 3518.28,2650.72 3521.28,2650.72 3542,2630 R17.2@3544,2628 ; 3645,2630 3668,2607 R20.2@3668,2581 ; 3854.64,2624.64 3855,2625 ; v1@3189.28,2330 v1@3189.28,2355 ; v1@3189.28,2355 v1@3189.28,2379 ; v1@3189.28,2379 v1@3189.28,2400 ; v1@3189.28,2400 v1@3189.28,2424 ; v1@3189.28,2424 v1@3189.28,2444 ; v1@3189.28,2444 v1@3189.28,2465 ; v1@3189.28,2465 v1@3189.28,2489 ; C11.1@3203.28,2274.73 3211,2274.73 3255.27,2274.73 3260,2270
  Top Layer w19.29: C11.1@3130,2273 3156,2299 ; v1(3187,2330) 3156,2299 ; C11.1@3203,2251 3205.27,2253.27 3211,2259 3211,2274.73 3211,2282.46 3211,2299 ; v1(3211,2330) 3211,2299 ; 3250,2300 3249,2299 3227.54,2299 3211,2299 ; 3156,2299 3189.28,2299 3211,2299
  Top Layer w20: C11.1@3130,2267 C11.1@3130,2273 ; C11.1@3197.53,2261.02 3203,2255.54 3205.27,2253.27 3219.53,2239.02 3225,2239.02 3225,2215
  Top Layer w39.37: 3046,2267 3130,2267 3191.54,2267 3193.54,2265 3197.53,2261.02 3203,2261.02 3203,2255.54 3203,2251 3203,2214
  Top Layer w50: 3046,2267 2847,2267 2843,2263 2843,2305.74 L1.2@2758.9,2389.84 2758.9,2330.1 2871,2218 3085,2218 3112,2245 C11.1@3140,2245 ; 3203,2214 3115,2214 3112,2217 C11.1@3140,2245 ; C11.1@3140,2245 3197,2245 3203,2251 3146,2251 C11.1@3140,2245
  Bottom Layer w5: C118.1@3145,1315 3157,1327 3164,1334 ; v1(3149,1356) 3149,1369 R98.2@3169,1389 ; v1@3169,1334 3175,1334 v1(3177,1334)
  Bottom Layer w9.84: v1(1624,2048) 1636,2060 1689,2060 1702,2073 1702,2327 1739,2364 1739,2521 1715,2545 1703,2545 R14.2@1700,2548
  Bottom Layer w10: TR3.1@1462.31,1234.57 1462.32,1253.32 1467,1258 1531,1258 C86.1@1577,1304 ; TR1.1@1466.31,555.57 1466.32,572.32 1471.32,572.32 1479,580 1539,580 C22.1@1573,614 ; TR5.1@1466.31,1917.57 1466.32,1933.32 1473,1940 1555,1940 1582,1967 C150.1@1582,1981 ; TR6.1@3042.31,1896.57 3042.32,1911.32 3051,1920 3115,1920 3127,1932 3127,1945 3151,1969 3155.01,1973.01 3162,1980 3162,1989 3162,1994.5 R146.2@3162,2035 ; TR4.1@3046.31,1242.57 3046.32,1261.32 3055,1270 3114,1270 3145,1301 C118.1@3145,1315 ; TR2.1@3048.31,557.57 3048.32,572.32 3056,580 3116,580 3144,608 C54.1@3144,627 ; v1@3148,449 v1(3148,471) ; 3158.28,1969 3178,1969 v1(3179,1968) ; v1(3191,448) v1(3191,470)
  Bottom Layer w11.81: v1(1558,1116) 1544,1130 v1(1544,1134) 1567,1134 v1(1568,1135)
  Bottom Layer w12: C118.1@3145,1315 3145,1328 3139,1334 C118.1@3149,1334 ; v1(3149,1356) C118.1@3149,1334 ; 3166,1332 v1@3169,1332 ; R98.2@3169,1389 R98.2@3169,1374 ; v1@3175,1327 3157,1327 3149,1327 C118.1@3149,1334 ; v1@3175,1332 v1@3169,1332 ; v1@3177,1327 3202,1327 v1(3203,1328) 3210,1335 v1(3210,1349) ; v1(3186,2489) v1@3186,2465 ; v1(3187,2465) v1@3186,2465 ; C118.1@3149,1334 3164,1334 v1@3169,1334 ; v1@3169,1332 v1@3169,1334 ; v1@3169,1334 v1@3169,1361 ; v1@3169,1361 3198,1361 v1(3210,1349) ; v1@3169,1361 R98.2@3169,1374 ; R98.2@3169,1374 v1(3210,1374) v1(3210,1349) ; v1@3186,2355 v1(3186,2379) ; v1@3186,2355 3186,2331 v1(3187,2330) v1(3211,2330) ; v1@3186,2355 v1(3187,2355) v1@3210,2355 ; v1(3186,2379) v1@3186,2400 ; v1(3186,2379) v1(3210,2379) ; v1@3186,2400 v1(3186,2424) ; v1@3186,2400 v1(3187,2400) v1@3210,2400 ; v1(3186,2424) v1(3210,2424) ; v1(3186,2424) v1(3186,2444) v1@3186,2465 ; v1@3210,2355 v1(3210,2379) ; v1@3210,2355 3210,2331 v1(3211,2330) ; v1@3210,2355 v1(3211,2355) v1@3233,2355 ; v1(3210,2379) v1@3210,2400 ; v1(3210,2379) v1(3233,2379) ; v1@3210,2400 v1(3210,2424) ; v1@3210,2400 v1(3211,2400) v1@3233,2400 ; v1(3210,2424) v1(3233,2424) ; v1(3211,2330) v1(3234,2330) ; v1@3233,2355 v1(3233,2379) ; v1@3233,2355 3233,2331 v1(3234,2330) ; v1@3233,2355 v1(3234,2355) v1(3257,2355) ; v1(3233,2379) v1@3233,2400 ; v1(3233,2379) v1(3257,2379) ; v1@3233,2400 v1(3233,2424) ; v1@3233,2400 v1(3234,2400) v1(3257,2400) ; v1(3233,2424) v1(3257,2424) ; v1(3234,2330) v1(3257,2330) ; v1(3257,2330) v1(3257,2355) ; v1(3257,2330) v1(3283,2330) v1(3283,2355) ; v1(3257,2355) v1(3283,2355) ; v1(3257,2355) v1(3257,2379) ; v1(3257,2379) v1(3282,2379) v1@3283,2379 ; v1(3257,2379) v1(3257,2400) ; v1(3257,2400) v1(3257,2424) ; v1(3257,2400) v1(3283,2400) ; v1(3257,2424) v1(3282,2424) 3283,2423 v1(3283,2400) ; v1(3283,2355) v1@3283,2379 ; v1@3283,2379 v1(3283,2400)
  Bottom Layer w17.72: v1@3143,1074 3143,1040 3152,1031 3156,1031 3156,1035 3148,1043 v1(3179,1074) ; C118.1@3145,1315 3157,1315 3161,1319 3175,1319 ; v1@3174,1119 v1(3175,1118) ; v1@3175,1104 v1(3181,1098) ; v1(3175,1355) 3175,1334 3175,1332 v1@3175,1327 ; v1(3177,1334) v1@3177,1327 ; v1(3179,1308) v1@3179,1315 ; v1(3188,1685) 3198,1695 v1@3198,1704 ; 3175,1319 3177,1319 ; 3175,1319 v1@3175,1327 ; v1@3175,1327 v1@3177,1327 ; 3177,1319 3179,1319 v1@3179,1317 ; 3177,1319 v1@3177,1327 ; 3177,1319 3177,1317 v1@3179,1317 ; v1@3179,1315 v1@3179,1317 ; v1@3179,1315 3181,1317 v1@3179,1317
  Bottom Layer w19.29: v1(1544,671) 1558,671 1548.5,661.5 1561,649 1567,655 ; C22.1@1559,624 C22.1@1566.53,624 C22.1@1567,624 ; C22.1@1567,616 C22.1@1567,624 ; v1(1568,1135) 1568,1133 v1@1591,1133 ; v1(1569,672) 1569,657 ; C22.1@1575,608 1590,623 v1(1609,623) 1609,631 v1@1610,632 ; R23.2@1580,707 1580,663 1588,655 ; 1581,2041 1572,2041 1559,2028 1564,2028 v1(1564,2024) ; R123.2@1582,1710 1582,1723 ; v1@1583,2023 1572,2012 C150.1@1579,2005 ; v1@1583,2030 v1@1589,2024 ; 1584,1075 1582,1077 ; 1584,1092 v1(1606,1114) ; R123.2@1587,1718 1582,1723 ; C150.1@1587,1983 C150.1@1584,1983 ; R74.2@1589,1407 1589,1367 ; v1(1591,1134) v1@1591,1133 ; v1(1592,670) 1592,659 ; 1605,1723 v1(1605,1755) 1598,1755 1597,1754 v1@1597,1773 ; v1(1606,466) 1606,459 v1(1595,448) v1@1595,447 ; v1(1608,647) v1@1608,643 ; v1@1609,2030 1609,2031 1608,2031 1607,2031 1607.5,2031.5 v1(1624,2048) 1623,2049 1590,2049 1582,2049 v1(1541,2049) 1541,2026 v1(1542,2026) 1542,2024 v1(1564,2024) ; v1(1614,670) 1614,658 ; v1(1615,1774) 1615,1766 1608,1773 v1@1597,1773 ; v1(1617,1795) v1@1597,1795 ; C82.1@2420,935 2420,892.5 L27.2@2422,890.5 ; 2421,245 2426,240 ; 2566,908 2581,893 v1(2581,885) ; 2572,98 2573,98 ; 2577,1562 2577,1539 v1(2586,1530) ; v1(2603,841) 2601,843 v1@2601,864 ; v1(2603,864) v1@2601,864 ; 2607,1557 v1(2607,1525) ; v1(2621,73) v1@2621,74 ; v1(3112,1074) v1(3135,1074) 3143,1074 v1(3157,1074) v1(3179,1074) ; v1(3115,1960) C182.1@3124,1969 ; v1(3115,1981) C182.1@3118.87,1984.87 ; C54.1@3129,642 v1(3129,671) ; v1(3148,471) v1@3169,471 ; v1(3154,1704) v1(3176,1704) v1@3198,1704 ; R50.2@3155,697 v1(3128,697) 3128,672 v1(3129,671) ; C54.1@3157,640 3157,655 ; v1(3157,669) 3157,655 ; v1@3157,671 v1(3129,671) ; v1(3169,470) v1@3169,471 ; v1(3175,1118) 3175,1104 v1@3175,1098 ; 3176,1089 3176,1093 v1(3181,1098) v1@3175,1098 ; v1(3180,1946) 3168.55,1958.13 3158.28,1969 ; 3189.96,1978.12 v1(3179,1968) ; 3189.97,1978.13 3190.29,1978.43 3190.5,1978.62 3192,1980 3192.32,1980.42 v1(3199,1989) ; 3191,426 v1(3191,448) 3190,449 v1@3169,449 ; v1(3191,470) 3190,471 v1@3169,471 ; v1(3198,1705) v1@3198,1704 ; v1(3199,1969) v1(3179,1968) ; v1(3202,1074) v1(3179,1074) ; R147.2@3205,1651 3173,1683 v1(3164,1683) 3166,1685 v1(3188,1685) v1(3211,1685) R147.2@3211,1657 ; v1(3210,679) v1@3206,679 ; v1(3210,703) 3206,699 v1@3206,679 ; 3221,1706 3219,1704 v1@3198,1704 ; L57.2@3926,1535.5 3956,1535.5 ; L37.2@3938.5,881 v1(3990,881) ; 3956.5,202 v1@3985,202 ; 3960.5,903 v1(3990,903) ; 3965.5,224 v1@3985,224 ; 3974,859 v1(3990,859) ; 3978,1623 v1@3978,1578 ; C51.1@3985,257.5 C51.1@3985,257.44 v1@3985,224 ; C179.1@3999,1628.5 C179.1@3999,1628.44 v1@3999,1574 ; v1(4004,1552) v1@3999,1552 ; v1(4004,1574) v1@3999,1574 ; v1@1560,1340 v1(1560,1361) v1@1582,1361 ; v1@1560,1340 1560,1315 1577,1315 C86.1@1577,1310 ; v1@1560,1340 v1(1561,1340) v1@1582,1340 ; 1560.52,1794 1560.52,1796 v1(1572,1796) v1@1572,1794 ; 1560.52,1794 1560.52,1774 v1@1568.04,1766.48 ; 1560.52,1794 v1@1568.04,1794 ; 1560.52,1794 1560,1794 1560,1745 1581,1724 ; v1(1564,2024) 1583,2024 v1(1586,2024) ; v1(1564,2024) 1564,2005 C150.1@1579,2005 ; C22.1@1567,624 1569,626 1569,655 ; C22.1@1567,624 1573,624 1589,624 1597,632 ; 1567,655 1569,655 ; 1567,655 1569,657 ; 1568.04,1756 v1@1568.04,1766.48 ; 1568.04,1756 1568.52,1756 ; 1568.04,1756 1568.52,1755.52 1568.52,1756 ; v1@1568.04,1766.48 v1@1568.04,1774 ; v1@1568.04,1766.48 v1@1568.52,1766 ; v1@1568.04,1774 v1@1568.04,1794 ; v1@1568.04,1774 v1(1572,1774) ; v1@1568.04,1794 v1@1572,1794 ; 1568.52,1756 1572,1756 1574,1754 v1@1574,1774 ; 1568.52,1756 v1@1568.52,1766 ; v1@1568.52,1766 1572,1769.48 v1(1572,1774) ; 1569,655 1588,655 ; 1569,655 1569,657 ; v1(1572,1774) v1@1574,1774 ; v1@1572,1794 v1@1574,1794 ; v1@1574,1774 v1@1574,1794 ; v1@1574,1774 v1@1577,1774 ; v1@1574,1794 v1@1581,1794 ; v1@1574,1794 1574,1795 v1@1581,1795 ; C86.1@1577,1310 1577,1304 1577,1303 1582,1303 C86.1@1582,1315 ; C86.1@1577,1310 C86.1@1582,1315 ; v1@1577,1774 v1@1581,1774 ; v1@1577,1774 1578,1773 v1@1581,1773 ; C150.1@1579,2005 1584.5,1999.5 C150.1@1585,1999.5 ; C150.1@1579,2005 C150.1@1585,2005 ; 1581,1724 v1@1581,1773 ; 1581,1724 1582,1723 ; v1@1581,1773 v1@1581,1774 ; v1@1581,1773 v1(1593,1773) v1@1597,1773 ; v1@1581,1774 v1@1581,1794 ; v1@1581,1794 v1@1581,1795 ; v1@1581,1794 v1(1595,1794) v1@1595,1795 ; v1@1581,1795 v1@1595,1795 ; 1582,1077 1558,1101 v1(1558,1116) v1@1582,1116 ; 1582,1077 v1(1582,1114) v1@1582,1116 ; v1@1582,1116 1604,1116 v1(1606,1114) ; C86.1@1582,1315 v1(1605,1338) ; C86.1@1582,1315 v1(1582,1339) v1@1582,1340 ; v1@1582,1340 1603,1340 v1@1604,1339 ; v1@1582,1340 v1(1582,1360) ; v1(1582,1360) v1@1583,1361 ; v1(1582,1360) 1589,1360 v1@1589,1361 ; v1(1582,1360) v1@1582,1361 ; v1@1582,1361 v1@1583,1361 ; v1@1583,1361 1589,1367 ; v1@1583,1361 v1@1589,1361 ; C150.1@1584,1983 1585.5,1984.5 1600.5,1999.5 ; C150.1@1584,1983 1582,1981 1579,1981 1577,1983 C150.1@1584,1983 ; C150.1@1585,1999.5 1600.5,1999.5 ; C150.1@1585,1999.5 C150.1@1585,2005 ; C150.1@1585,2005 C150.1@1586,2005 ; C150.1@1586,2005 v1@1607,2005 ; C150.1@1586,2005 v1(1586,2024) ; v1(1586,2024) v1@1589,2024 ; 1588,655 1592,659 ; 1588,655 1590,655 ; v1@1589,1361 v1@1604,1361 ; v1@1589,1361 1589,1367 ; v1@1589,2024 v1@1607,2006 ; v1@1589,2024 v1(1609,2024) v1@1609,2006 ; 1590,655 1592,655 ; 1590,655 1592,657 ; v1@1591,1133 v1(1616,1133) 1606,1123 v1(1606,1114) ; v1@1592,404 1592,422 v1(1595,425) ; v1@1592,404 1591,404 1590,403 1592,403 v1(1616,403) 1615,404 v1(1615,425) ; v1@1592,404 v1(1596,404) 1595,405 v1(1595,425) ; 1592,655 1611,655 1614,658 ; 1592,655 1592,641 1590,639 1597,632 ; 1592,655 1592,657 ; 1592,657 1592,659 ; v1(1595,425) v1@1595,447 ; v1(1595,425) v1(1615,425) ; v1@1595,447 v1(1615,447) v1(1615,425) ; v1@1595,1795 v1@1597,1795 ; 1597,632 v1@1608,643 ; v1@1597,1773 v1@1597,1795 ; 1600.5,1999.5 1614,1999.5 v1(1614,2001) ; 1600.5,1999.5 1602,2001 v1(1614,2001) ; v1@1604,1339 v1(1605,1338) ; v1@1604,1339 v1(1604,1359) v1@1604,1361 ; v1@1604,1361 1621,1361 v1(1625,1357) 1624,1357 v1(1605,1338) ; v1@1607,2005 v1@1607,2006 ; v1@1607,2005 1607,2004 1609,2004 v1@1608,2005 ; v1@1607,2005 v1@1608,2005 ; v1@1607,2006 v1@1609,2006 ; v1@1607,2006 v1@1608,2005 ; v1@1608,643 1608,634 v1@1610,632 ; v1@1608,2005 1609,2005 v1@1610,2005 ; v1@1609,2006 v1@1610,2005 ; v1@1610,632 1610,648 1614,652 1614,658 ; v1@1610,2005 1614,2005 v1(1614,2001) ; v1@1610,2005 v1(1614,2001) ; 2573,98 v1(2598,73) ; 2573,98 v1(2597,98) ; v1@2581,863 v1(2581,885) ; v1@2581,863 2581,842 v1(2582,841) v1(2582,863) ; v1@2581,863 v1(2582,863) ; v1(2581,885) 2584,882 v1@2598,882 ; v1(2582,863) 2582,866 v1@2598,882 ; v1@2586,1508 v1(2586,1530) ; v1@2586,1508 2586,1487 v1(2587,1486) 2591,1482 v1(2608,1482) 2607,1483 v1(2607,1504) ; v1@2586,1508 v1(2587,1508) 2591,1504 v1(2607,1504) ; v1(2586,1530) 2591,1525 v1(2607,1525) ; v1(2597,98) v1@2602.5,92.5 ; v1(2597,98) 2597,104 2598,105 v1@2598,103 ; v1(2597,98) v1@2598,99 ; v1(2598,73) v1@2599,74 ; v1(2598,73) 2598,88 v1@2602.5,92.5 ; v1@2598,99 v1@2598,103 ; v1@2598,99 v1@2602,103 ; v1@2598,103 v1@2602,103 ; v1@2598,882 v1(2601,885) v1@2601,864 ; v1@2599,74 v1@2621,74 ; v1@2599,74 2599,82 v1@2621,82 ; v1@2602,103 2604,105 2613,105 v1(2620,98) 2627,105 2636,105 v1(2643,98) v1@2643,75 ; v1@2602,103 2613,103 v1@2602.5,92.5 ; v1(2607,1504) v1(2607,1525) ; v1@2621,74 v1(2644,74) v1@2643,75 ; v1@2621,74 v1@2621,82 ; v1@2621,82 2636,82 v1@2643,75 ; C182.1@3118.87,1984.87 C182.1@3124.16,1984.87 ; C182.1@3118.87,1984.87 3123,1989 C182.1@3126.54,1989 ; C182.1@3124,1969 3151,1969 3158.28,1969 ; C182.1@3124,1969 3124.16,1969.16 C182.1@3124.16,1984.87 ; C182.1@3124.16,1984.87 C182.1@3126.54,1989 ; C182.1@3126.54,1989 C182.1@3142,1989 ; C182.1@3126.54,1989 3130,1995 R146.2@3162,2035 ; C182.1@3142,1989 3150.77,1978.22 3153.25,1975.17 3155.01,1973.01 3155.83,1972 3158.28,1969 ; C182.1@3142,1989 3162,1989 3167,1989 ; 3157,655 v1(3180,655) v1(3206,655) v1@3206,679 ; 3158.28,1969 v1(3179,1968) ; R146.2@3162,2035 3189.03,1997.16 3189.36,1996.69 3192,1993 v1(3199,1989) ; R146.2@3162,2035 3160,1995 3162,1994.5 3179.06,1990.24 v1@3180,1990 ; 3167,1989 v1@3180,1989 ; 3167,1989 3179.01,1989.92 v1@3180,1990 ; v1@3169,449 3148,449 v1(3148,447) 3148,435 3169,414 v1(3169,447) v1@3169,449 ; v1@3175,1098 3175,1078 v1(3179,1074) ; v1@3180,1989 v1@3180,1990 ; v1@3180,1989 v1(3199,1989) ; 3956,1535.5 3978,1557.5 v1@3978,1574 ; 3956,1535.5 3976.5,1535.5 v1(3982,1530) ; v1@3978,1574 v1@3978,1578 ; v1@3978,1574 v1(3982,1574) ; v1@3978,1578 v1(3982,1574) ; v1(3982,1530) v1(3982,1552) v1(3982,1574) ; v1(3982,1530) v1(4004,1530) 3999,1535 v1@3999,1552 ; v1@3985,202 v1@3985,224 ; v1@3985,202 3985,184 v1(3988,181) 4008,181 v1(4009,180) 4011,182 v1@4011,202 ; v1@3985,202 v1(3988,202) v1(4010,202) v1@4011,202 ; v1@3985,224 v1(3989,224) v1(4011,224) v1@4011,202 ; v1(3990,859) v1(4012,859) v1(4012,881) ; v1(3990,859) v1(3990,881) ; v1(3990,881) v1(4012,881) ; v1(3990,881) v1(3990,903) ; v1(3990,903) 3990,925.5 3998,933.5 4012,919.5 v1(4012,903) ; v1(3990,903) v1(4012,903) ; v1@3999,1552 v1@3999,1574 ; v1(4012,881) v1(4012,903)
  Bottom Layer w19.68: R122.2@1582,2057 1582,2049 R122.2@1582,2042 ; C150.1@1587,1983 1585.5,1984.5 1572,1998 1579,2005 1583,2009 1583,2023 1583,2024 1583,2030 1581,2030 1581,2041 1582,2041 ; C115.1@3944,953 L37.2@3944,886.5 ; 3960.5,903 L37.2@3944,886.5 ; 3974,859 3959,874 3936.5,874 3934,876.5 3938.5,881 L37.2@3944,886.5 ; 1582,2041 1583,2041 R122.2@1582,2042 ; 1582,2041 R122.2@1582,2042
  Bottom Layer w20: R122.2@1582,2057 1590,2049 1607.5,2031.5 1608,2031 1609,2030 v1(1609,2024) ; v1@1609,2004 1609,2005 v1@1609,2006 ; C146.1@2402,1615 2434,1615 ; C18.1@2404,262 C18.1@2406.5,259.5 ; C82.1@2420,935 2428.5,926.5 C83.1@2491,926.5 ; L7.2@2421,221.5 2421,245 C18.1@2406.5,259.5 ; L47.2@2431,1569.5 2434,1572.5 2434,1601 ; C147.1@2452.5,1615 2434,1615 ; C147.1@2456,1618.5 2460.5,1614 2550,1614 2607,1557 ; C19.1@2459,259.5 C18.1@2406.5,259.5 ; 2577,1562 2540,1599 2436,1599 2434,1601 ; R50.2@3155,697 R50.2@3167,697 ; v1(3157,669) 3157,671 3167,671 R50.2@3167,697 ; R50.2@3167,701 R50.2@3167,697 ; R51.2@3169,414 3174,409 3191,426 ; C50.1@3935,276 C50.1@3936,275 ; C178.1@3945,1623 3978,1623 3993.5,1623 C179.1@3999,1628.5 ; 3956.5,202 3952,206.5 L17.2@3948,206.5 ; 3965.5,224 L17.2@3948,206.5 ; C51.1@3985,257.5 3953.5,257.5 C50.1@3936,275 ; 2434,1601 2434,1615 ; C50.1@3936,275 L17.2@3936,206.56 3936,206.5 L17.2@3948,206.5
  Bottom Layer w22: C22.1@1567,616 C22.1@1573,622 ; C22.1@1573,624 C22.1@1573,622 ; C22.1@1575,608 1573,610 1573,614 C22.1@1573,622 ; R123.2@1582,1710 R123.2@1587,1705 ; R123.2@1587,1718 R123.2@1587,1705 ; 1605,1723 R123.2@1587,1705 ; C147.1@2452.5,1615 C147.1@2456,1618.5 ; C83.1@2491,926.5 2547.5,926.5 2566,908
  Bottom Layer w22.05: C54.1@3129,642 3144,627 C54.1@3157,640
  Bottom Layer w23: 1582,1077 1582,1028 R75.2@1584,1026 ; 1584,1092 1584,1075 1584,1043 ; C19.1@2459,259.5 2523.5,259.5 2562,221 2562,108 2572,98 ; R75.2@1584,1026 R75.2@1584,1028 ; R75.2@1584,1026 1585,1025 R75.2@1585,1027 ; R75.2@1584,1028 1584,1043 ; R75.2@1584,1028 R75.2@1585,1027 ; 1584,1043 1585,1042 R75.2@1585,1027
  Bottom Layer w24: L7.2@2421,215.5 L7.2@2421,215.56 2421,221.5 C19.1@2459,259.5 ; R147.2@3205,1651 R147.2@3211,1657
  Bottom Layer w25: R24.2@1592,346 1592,403 v1@1592,404
  other v1: 3179,1990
